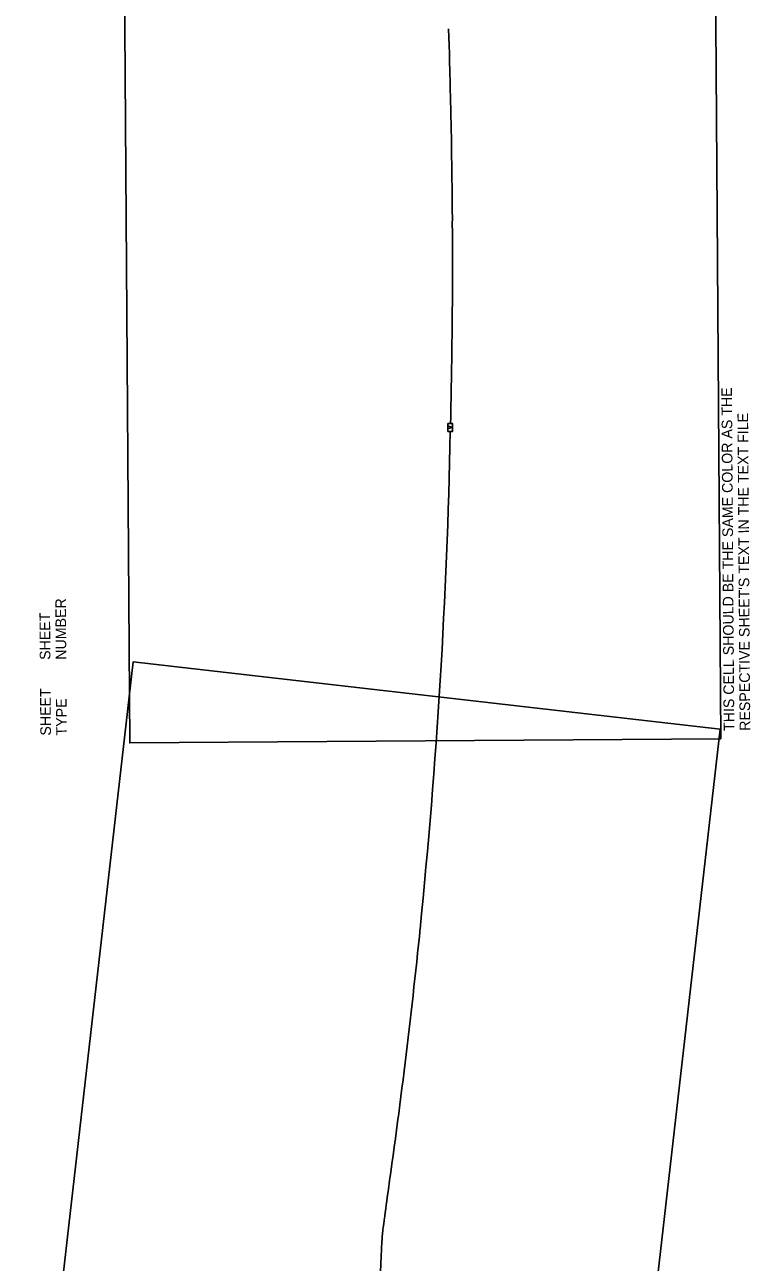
# Model space of a CAD drawing. Extents: x 601462 to 605493, y 331960 to 402715.
# Drawn here: x 602322 to 603519, y 361319 to 363361 of the extents above; entities that cross this region are included whole.
import ezdxf

# ---------------------------------------------------------------- set-up
doc = ezdxf.new("R2010")
doc.units = 0
for name, color, linetype in [('P_FTMS', 7, 'Continuous'), ('P_FTMSConduit', 7, 'Continuous'), ('P_MISC_TXT_1A (Construction)', 7, 'Continuous'), ('P_MISC_TXT_1B (Construction)', 7, 'Continuous')]:
    doc.layers.add(name, color=color, linetype=linetype)

# ---------------------------------------------------------------- blocks, each defined once
blk = doc.blocks.new('FTMS_FCV')
at = {"layer": 'P_FTMS'}
blk.add_line((13, 16), (1, -22), dxfattribs=at)
blk.add_lwpolyline([(39, 24), (-39, 24), (-39, -24), (39, -24)], close=True, dxfattribs=at)
blk.add_lwpolyline([(-12, 16), (1, -22)], dxfattribs=at)

msp = doc.modelspace()

# ---------------------------------------------------------------- linework, layer by layer
at = {"layer": 'P_FTMSConduit'}
for points in [[(603027.2, 362868.1), (603027.7, 362923.8), (603027.7, 362936.3), (603027.7, 362956.3), (603027.6, 362967.8), (603027.6, 362977.5), (603027.7, 362984.5), (603027.7, 362994.6), (603027.6, 363006.3), (603027.6, 363018.8), (603027.4, 363032.9), (603027.5, 363042.3), (603027.4, 363054), (603027.3, 363067.1), (603027.2, 363079.2), (603027.1, 363089.4), (603026.9, 363095.8), (603026.8, 363104.7), (603026.6, 363115.7), (603026.5, 363125.4), (603026.5, 363133.4), (603026.1, 363141.1), (603026.2, 363147.7), (603026.2, 363156.6), (603026.1, 363162.3), (603026, 363169.6), (603025.8, 363177.4), (603025.7, 363185.1), (603025.6, 363192.8), (603025.4, 363197.5), (603025.3, 363201.6), (603025.2, 363206), (603025.1, 363210.2), (603025, 363216.7), (603024.8, 363219.6), (603024.7, 363224.8), (603024.5, 363232.2), (603024.4, 363240), (603024.2, 363246.3), (603024.1, 363250.7), (603023.9, 363254.4), (603023.8, 363260.8), (603023.7, 363269.6), (603023.4, 363279.7), (603023.3, 363287), (603022.8, 363298.3), (603022.6, 363306.4), (603022.5, 363313.6), (603022.1, 363327.2), (603021.1, 363354.7)], [(602892.8, 360942.1), (602911.3, 361353.5)]]:
    msp.add_lwpolyline(points, dxfattribs=at)
for centre, radius, start, end in [((579272.3, 363176.4), 23756.9, 358.85844, 359.25655), ((592867.9, 362895.6), 10158.2, 354.19856, 358.84195), ((592266.6, 362955.3), 10762.6, 351.83237, 354.21761), ((591460.3, 362945.5), 11560, 352.19898, 352.44882), ((603161, 361342.5), 250, 172.199, 177.4806)]:
    msp.add_arc(centre, radius, start, end, dxfattribs=at)
at = {"layer": 'P_MISC_TXT_1A (Construction)'}
msp.add_lwpolyline([(603290.7, 360634.3), (603469.4, 362199.1), (602500.7, 362309.8), (602322, 360745)], close=True, dxfattribs=at)
at = {"layer": 'P_MISC_TXT_1B (Construction)'}
msp.add_lwpolyline([(603470.1, 362182.9), (603459.3, 363757.9), (602484.4, 363751.2), (602495.1, 362176.2)], close=True, dxfattribs=at)

# ---------------------------------------------------------------- block references
at = {"layer": 'P_FTMS', "xscale": 0.16404166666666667, "yscale": 0.16404166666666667, "rotation": 90.21124366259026}
msp.add_blockref('FTMS_FCV', (603023.9, 362696.7), dxfattribs=at)

# ---------------------------------------------------------------- texts
at = {"layer": 'P_MISC_TXT_1B (Construction)'}
for s, p in [('THIS CELL SHOULD BE THE SAME COLOR AS THE', (603492.6, 362196)), ("RESPECTIVE SHEET'S TEXT IN THE TEXT FILE", (603518.9, 362196.2)), ('NUMBER', (602390.6, 362313.5)), ('SHEET', (602364.3, 362313.3)), ('SHEET', (602365.2, 362188.3)), ('TYPE', (602391.4, 362188.5))]:
    msp.add_text(s, height=17.5, rotation=90.3915, dxfattribs=at).set_placement(p)

doc.saveas('drawing.dxf')
